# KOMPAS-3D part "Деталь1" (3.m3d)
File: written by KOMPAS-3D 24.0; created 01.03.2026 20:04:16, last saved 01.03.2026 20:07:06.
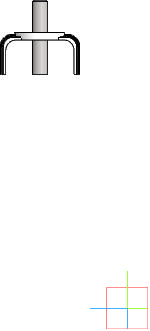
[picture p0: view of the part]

Document properties: Автор: R2D2; Полное имя файла: E:\Работа\Зайцев\GVWR3131M-2W-F-S Задвижка клиновая с выдвижным штоком DN.ru Ду50-200 Ру63\DN80\исходные материалы\3.m3d

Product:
- Body: Твердое тело1  | qty 1
    Масса: 0.546953
- Part/product: Деталь1
    Масса: 0.546953
    additional columns: Типовые

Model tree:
1. Твердое тело1  (labels: Твердое тело1)
2. Эскиз:1
3. Элемент выдавливания:1
     Расстояние 1 = 500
